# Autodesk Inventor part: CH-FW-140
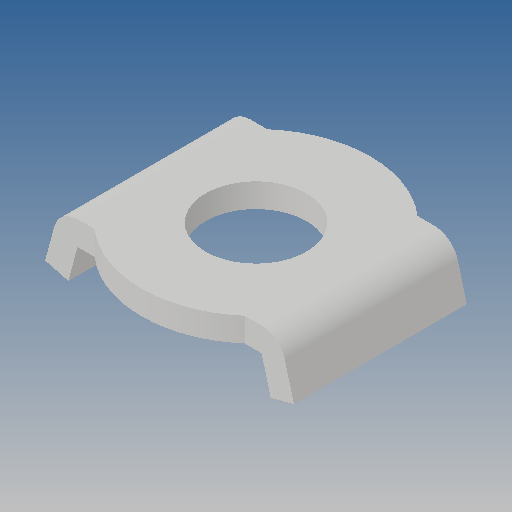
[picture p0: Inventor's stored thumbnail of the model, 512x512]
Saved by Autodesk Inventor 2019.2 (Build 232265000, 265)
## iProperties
Created: 2015-08
Part Number: CH-FW-140
Material: Ogólny
Document SubType Name: Modeling
Designer: CADENGINEERING4
Density: 1 g/cm^3
Appearance: Domyślna
Author: CADENGINEERING4
Revision Number: ÈÎºÎ
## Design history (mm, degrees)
feature "ÇÐ³ý-À­Éì1"
node "Bryła1"
